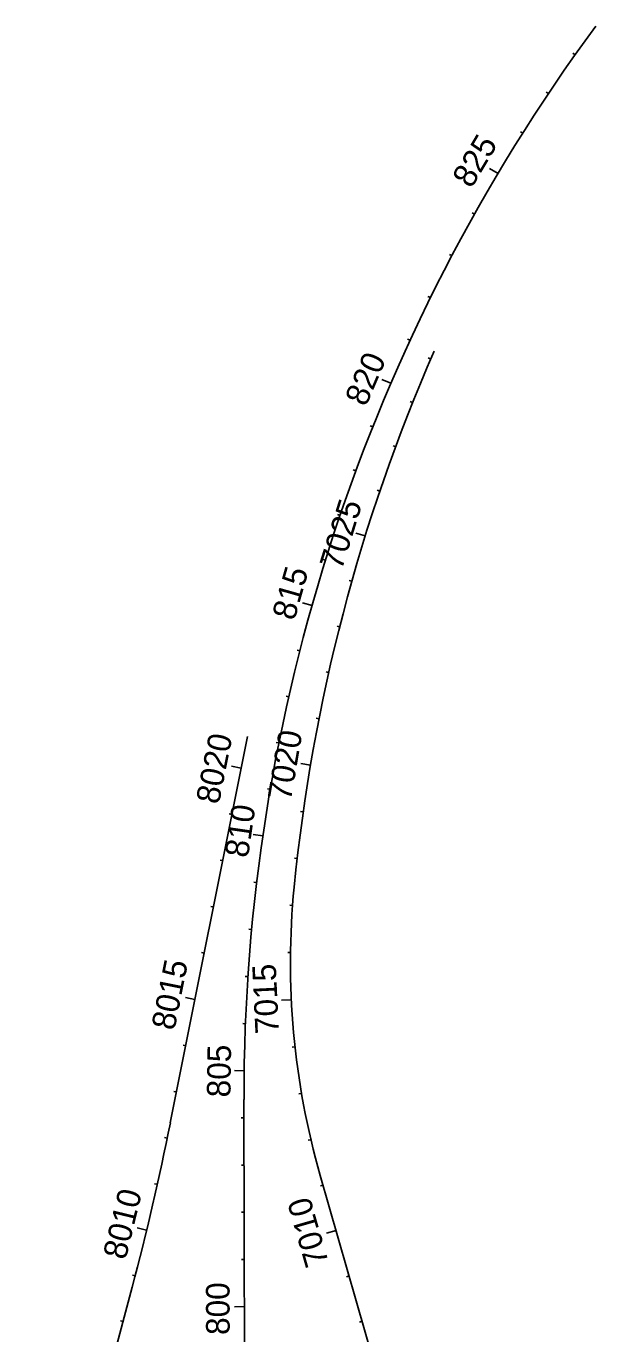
# Model space of a CAD drawing. Extents: x 448091 to 665917, y 1461380 to 1587607.
# Drawn here: x 452794 to 454001, y 1506458 to 1509230 of the extents above; entities that cross this region are included whole.
import ezdxf

# ---------------------------------------------------------------- set-up
doc = ezdxf.new("R2010")
doc.units = 0
doc.layers.add('TextShtNo', color=7, linetype='Continuous')
doc.layers.add('TextTitle', color=7, linetype='Continuous')

msp = doc.modelspace()

# ---------------------------------------------------------------- linework, layer by layer
at = {"layer": 'TextShtNo'}
for p, q in [((453099.3, 1506905.3), (453262.8, 1507723.9)), ((453262.6, 1503420), (453255.5, 1506954.9)), ((453726.1, 1505715.5), (453417.2, 1506793.2)), ((452793.6, 1505710.7), (453018.3, 1506556.8))]:
    msp.add_line(p, q, dxfattribs=at)
for centre, radius, start, end in [((457075.2, 1506962.6), 3819.7, 143.5827, 180.1156), ((457094.6, 1507036.8), 3750.9, 156.36, 174.3675), ((454990.9, 1507244.3), 1637, 174.3675, 195.9938), ((447480.7, 1508027.3), 5729.6, 345.12859, 348.70686)]:
    msp.add_arc(centre, radius, start, end, dxfattribs=at)
at = {"layer": 'TextTitle'}
for p, q in [((453957.5, 1509169.5), (453952.9, 1509172.8)), ((453900.8, 1509087.1), (453896.1, 1509090.3)), ((453846.3, 1509003.3), (453841.5, 1509006.4)), ((453794, 1508918.1), (453776.2, 1508928.7)), ((453743.9, 1508831.5), (453738.9, 1508834.3)), ((453696.2, 1508743.7), (453691.1, 1508746.3)), ((453650.7, 1508654.6), (453645.5, 1508657.1)), ((453607.6, 1508564.4), (453602.4, 1508566.8)), ((453651.3, 1508524.4), (453646, 1508526.7)), ((453566.8, 1508473), (453547.8, 1508481.3)), ((453612.8, 1508432.1), (453607.5, 1508434.3)), ((453528.5, 1508380.7), (453523.2, 1508382.8)), ((453576.9, 1508338.8), (453571.5, 1508340.8)), ((453492.6, 1508287.4), (453487.2, 1508289.4)), ((453543.4, 1508244.6), (453538, 1508246.4)), ((453459.1, 1508193.1), (453453.7, 1508195)), ((453512.5, 1508149.5), (453492.7, 1508155.6)), ((453428.2, 1508098), (453422.7, 1508099.8)), ((453484.1, 1508053.6), (453478.6, 1508055.2)), ((453399.7, 1508002.2), (453379.7, 1508007.8)), ((453458.3, 1507957), (453452.7, 1507958.4)), ((453373.7, 1507905.6), (453368.2, 1507907)), ((453435, 1507859.7), (453429.4, 1507861)), ((453350.3, 1507808.4), (453344.7, 1507809.7)), ((453414.4, 1507761.9), (453408.8, 1507763)), ((453329.5, 1507710.6), (453323.8, 1507711.7)), ((453249.5, 1507657.2), (453229.1, 1507661.3)), ((453396.4, 1507663.5), (453375.9, 1507667)), ((453311.2, 1507612.3), (453305.5, 1507613.3)), ((453229.9, 1507559.1), (453224.2, 1507560.3)), ((453381, 1507564.7), (453375.3, 1507565.5)), ((453295.4, 1507513.5), (453274.9, 1507516.5)), ((453210.3, 1507461.1), (453204.7, 1507462.2)), ((453368.2, 1507465.5), (453362.5, 1507466.2)), ((453282.3, 1507414.4), (453276.6, 1507415.1)), ((453358.4, 1507366), (453352.7, 1507366.5)), ((453190.7, 1507363), (453185.1, 1507364.1)), ((453271.8, 1507315), (453266.1, 1507315.5)), ((453171.1, 1507265), (453165.5, 1507266.1)), ((453354, 1507266.1), (453348.3, 1507266.2)), ((453263.9, 1507215.3), (453258.1, 1507215.7)), ((453151.5, 1507166.9), (453131.2, 1507171)), ((453355.7, 1507166.2), (453335, 1507165.2)), ((453258.6, 1507115.4), (453252.8, 1507115.7)), ((453132, 1507068.8), (453126.3, 1507070)), ((453363.5, 1507066.5), (453357.8, 1507065.9)), ((453255.9, 1507015.5), (453235.1, 1507015.8)), ((453112.4, 1506970.8), (453106.7, 1506971.9)), ((453377.4, 1506967.5), (453371.8, 1506966.5)), ((453255.6, 1506915.5), (453249.8, 1506915.5)), ((453092.7, 1506872.7), (453087.1, 1506873.9)), ((453397.3, 1506869.5), (453391.7, 1506868.2)), ((453255.8, 1506815.5), (453250, 1506815.5)), ((453071.7, 1506775), (453066.1, 1506776.2)), ((453423.1, 1506772.9), (453417.5, 1506771.3)), ((453256, 1506715.5), (453250.2, 1506715.5)), ((453049, 1506677.6), (453028.8, 1506682.5)), ((453450.6, 1506676.8), (453430.7, 1506671)), ((453256.2, 1506615.5), (453250.4, 1506615.5)), ((453024.6, 1506580.6), (453019, 1506582)), ((453478.2, 1506580.6), (453472.6, 1506579)), ((453256.4, 1506515.5), (453235.7, 1506515.4)), ((452999, 1506483.9), (452993.4, 1506485.4)), ((453505.7, 1506484.5), (453500.2, 1506482.9))]:
    msp.add_line(p, q, dxfattribs=at)

# ---------------------------------------------------------------- texts
for s, rotation, p in [('825', 59.2069, (453737.4, 1508884.4)), ('820', 66.7069, (453513.7, 1508421.8)), ('7025', 72.7441, (453462.5, 1508075.1)), ('815', 74.2069, (453362.3, 1507968.2)), ('8020', 78.7069, (453202.2, 1507578.9)), ('7020', 80.3816, (453354.7, 1507586.2)), ('810', 81.7069, (453263.9, 1507465.6)), ('8015', 78.7069, (453107.9, 1507099.6)), ('7015', 92.7344, (453329.8, 1507094.8)), ('805', 89.2069, (453226.7, 1506959)), ('8010', 76.3749, (453004.5, 1506613.1)), ('7010', 105.9938, (453435.7, 1506608.1)), ('800', 90.1156, (453225.1, 1506455.6))]:
    msp.add_text(s, height=50, rotation=rotation, dxfattribs=at).set_placement(p)

doc.saveas('drawing.dxf')
